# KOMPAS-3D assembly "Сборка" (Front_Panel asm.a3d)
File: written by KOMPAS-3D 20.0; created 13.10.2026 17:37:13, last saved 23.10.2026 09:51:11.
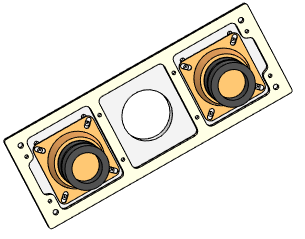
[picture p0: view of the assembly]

Document properties: Полное имя файла: D:\RicWork\Project-EPS32\box_compas\корпус\Front_Panel asm.a3d

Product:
- Part/product: Сборка
    Масса: 1.30703
  - Component [detail]: Деталь  | qty 2  | Масса: 0.317349; source file: ..\динамик\4om10w.m3d
  - Component [detail]: Деталь  | Материал: Фанера, береза,ФСФ ВВ/С ГОСТ 3916.1-2018 (density 760 kg/m3); Масса: 0.0539472; source file: front_panel_original.m3d
  - Component [detail]: Деталь  | Масса: 0.184328; source file: gril_panel.m3d
  - Component [detail]: Деталь  | qty 2  | Масса: 0.217029; source file: ..\динамик\SOTAMIA мини-динамики 2 дюйма 10 Вт 4-8 Ом.m3d

Referenced files in D:\RicWork\Project-EPS32\box_compas\корпус\: gril_panel.m3d, front_panel_original.m3d
Referenced files in D:\RicWork\Project-EPS32\box_compas\динамик\: 4om10w.m3d, SOTAMIA мини-динамики 2 дюйма 10 Вт 4-8 Ом.m3d
Referenced files in D:\myProjects\Progect_esp32\box_compas\динамик\: 4om10w.m3d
